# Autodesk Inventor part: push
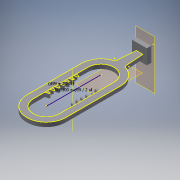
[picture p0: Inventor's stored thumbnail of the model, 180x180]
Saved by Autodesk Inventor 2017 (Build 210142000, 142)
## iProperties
Created: 2017-05
Part Number: push
Material: Generic
Document SubType Name: Modeling
Designer: 1717440
Density: 1 g/cm^3
Appearance: Default
Author: 1717440
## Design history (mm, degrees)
workplane "Work Plane1"
sketch "Sketch1"
  geometry: L1 (0, 3.175)-(17, 3.175) reference; L2 (17, 3.175)-(0, 3.175); L3 (0, 3.175)-(0, 20.175); L4 (0, 20.175)-(17, 20.175); L5 (17, 20.175)-(17, 3.175); 1 further point
  constraints: 8 end point, 2 parallel, 1 horizontal, 1 perpendicular
  dimensions: "d0" = 17 distance of L2.end L3.end
extrude "Extrusion1" new body sketch "Sketch1" distance "d1" = 5; taper "d2" = 0 deg
workplane "Work Plane2"
sketch "Sketch2" dims "d68" = 10, "d80" = 10
  geometry: L1 (-38.705, -3.689)-(1.295, -3.689); L2 (-18.705, -3.689)-(-18.705, 6.001); L3 (-39.255, -7.416)-(-39.255, 0.038); L4 (68.82, -3.689)-(5.82, -3.689); L5 (68.82, 11.311)-(5.82, 11.311); L6 (5.82, -18.689)-(68.82, -18.689); L7 (5.82, 11.311)-(8.32, 6.981); L8 (5.82, 11.311)-(10.82, 11.311); L9 (8.32, 6.981)-(9.82, 6.981); L10 (9.82, 6.981)-(12.32, 11.311); L11 (5.82, 11.311)-(12.32, 11.311); L12 (13.92, 11.311)-(16.42, 6.981); L13 (16.42, 6.981)-(17.92, 6.981); L14 (17.92, 6.981)-(20.42, 11.311); L15 (13.92, 11.311)-(20.42, 11.311); L16 (22.02, 11.311)-(24.52, 6.981); L17 (24.52, 6.981)-(26.02, 6.981); L18 (26.02, 6.981)-(28.52, 11.311); L19 (22.02, 11.311)-(28.52, 11.311); L20 (30.12, 11.311)-(32.62, 6.981); L21 (32.62, 6.981)-(34.12, 6.981); L22 (34.12, 6.981)-(36.62, 11.311); L23 (30.12, 11.311)-(36.62, 11.311); L24 (38.22, 11.311)-(40.72, 6.981); L25 (40.72, 6.981)-(42.22, 6.981); L26 (42.22, 6.981)-(44.72, 11.311); L27 (38.22, 11.311)-(44.72, 11.311); L28 (46.32, 11.311)-(48.82, 6.981); L29 (48.82, 6.981)-(50.32, 6.981); L30 (50.32, 6.981)-(52.82, 11.311); L31 (46.32, 11.311)-(52.82, 11.311); L32 (15.17, 9.146)-(19.17, 9.146); L33 (54.42, 11.311)-(56.92, 6.981); L34 (56.92, 6.981)-(58.42, 6.981); L35 (58.42, 6.981)-(60.92, 11.311); L36 (54.42, 11.311)-(60.92, 11.311); L37 (59.67, 9.146)-(55.67, 9.146); L38 (13.82, -18.689)-(16.32, -14.359); L39 (13.82, -18.689)-(18.82, -18.689); L40 (16.32, -14.359)-(17.82, -14.359); L41 (17.82, -14.359)-(20.32, -18.689); L42 (13.82, -18.689)-(20.32, -18.689); L43 (21.82, -18.689)-(28.32, -18.689); L44 (25.82, -14.359)-(28.32, -18.689); L45 (24.32, -14.359)-(25.82, -14.359); L46 (21.82, -18.689)-(24.32, -14.359); L47 (29.82, -18.689)-(36.32, -18.689); L48 (33.82, -14.359)-(36.32, -18.689); L49 (32.32, -14.359)-(33.82, -14.359); L50 (29.82, -18.689)-(32.32, -14.359); L51 (37.82, -18.689)-(44.32, -18.689); L52 (41.82, -14.359)-(44.32, -18.689); L53 (40.32, -14.359)-(41.82, -14.359); L54 (37.82, -18.689)-(40.32, -14.359); L55 (45.82, -18.689)-(52.32, -18.689); L56 (49.82, -14.359)-(52.32, -18.689); L57 (48.32, -14.359)-(49.82, -14.359); L58 (45.82, -18.689)-(48.32, -14.359); L59 (53.82, -18.689)-(60.32, -18.689); L60 (57.82, -14.359)-(60.32, -18.689); L61 (56.32, -14.359)-(57.82, -14.359); L62 (53.82, -18.689)-(56.32, -14.359); L63 (61.82, -18.689)-(68.32, -18.689); L64 (65.82, -14.359)-(68.32, -18.689)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; A1 r 15 centre (68.82, -3.689) between (68.82, -18.689) and (68.82, 11.311); A2 r 15 centre (5.82, -3.689) between (5.82, 11.311) and (5.82, -18.689); A3 r 22.5 centre (5.82, -3.689) between (-15.485, -10.922) and (5.82, -26.189); A4 r 22.5 centre (68.82, -3.689) between (68.82, -26.189) and (68.82, 18.811); A5 r 3 centre (-18.326, -11.887) between (-15.485, -10.922) and (-18.117, -8.894); A6 r 3 centre (-18.326, 4.509) between (-18.117, 1.516) and (-15.485, 3.545); A7 r 22.5 centre (5.82, -3.689) between (5.82, 18.811) and (-15.485, 3.545); 5 further points
  constraints: 154 end point, 17 point on circle, 10 horizontal, 10 midpoint, 7 centre point, 6 tangent, 5 point on line, 4 symmetric about line, 3 equal length, 2 collinear, 2 parallel, 1 perpendicular, 1 vertical, 101 other
  dimensions: "d45" = 30 diameter of A2; "d46" = 93 distance of point (83.82, -3.689) point (-9.18, -3.689); "d47" = 40 distance of L1.start L1.end; "d54" = 7.45397 distance of L3.start L3.end; "d59" = 5 distance of L5.end L7.end; "d60" = 60 deg angle of L7 L8; "d61" = 1.5 distance of L7.end L9.end; "d62" = 120 deg angle of L10 L9; "d65" = 8.1 distance of L5.end L12.start; "d70" = 5 distance of L38.start L38.end; "d71" = 60 deg angle of L39 L38; "d72" = 8 distance of L6.start L38.start; "d73" = 1.5 distance of L38.end L40.end; "d74" = 120 deg angle of L40 L41; "d77" = 8 distance of L38.start L43.start; "d82" = 7.5 radial gap between concentric circles of A1 A4; "d83" = 28 distance of L3.start L75.end; "d84" = 4 deg angle of L71 L72; "d85" = 28 distance of L3.end L75.start; "d86" = 4 deg angle of L74 L73; "d87" = 3 radius of A5 (derived); "d109" = 45 distance between parallel lines of L70 L69 (derived)
extrude "Extrusion6" join sketch "Sketch2" distance "d88" = 5; taper "d89" = 0 deg
sketch "Sketch3"
  geometry: L1 (-3.689, -68.82)-(-3.689, -5.82); L2 (7.416, -74.703)-(-14.794, -74.703); L3 (-14.794, -74.703)-(-14.794, 0.062); L4 (-14.794, 0.062)-(7.416, 0.062); L5 (7.416, 0.062)-(7.416, -74.703); L6 (7.416, -74.703)-(-14.794, 0.062); L7 (-14.794, -74.703)-(7.416, 0.062); A1 r 15 centre (-3.689, -5.82) between (11.311, -5.82) and (-18.689, -5.82) reference; A2 r 15 centre (-3.689, -68.82) between (-18.689, -68.82) and (11.311, -68.82) reference; 2 further points
  constraints: 14 end point, 3 midpoint, 2 parallel, 1 horizontal, 1 perpendicular, 1 vertical
extrude "Extrusion7" cut sketch "Sketch3" stored distance "d90" = 0; taper "d91" = 0 deg
sketch "Sketch4"
  geometry: L1 (7.416, -48.569)-(7.416, -50.572) reference; L2 (7.416, -50.572)-(11.311, -52.82) reference; L3 (11.311, -52.82)-(11.311, -54.42) reference; L4 (11.311, -54.42)-(9.146, -55.67) reference; L5 (9.146, -55.67)-(9.146, -59.67) reference; L6 (9.146, -59.67)-(11.311, -60.92) reference; L7 (-18.689, -68.32)-(-14.794, -66.072) reference; L8 (-14.794, -66.072)-(-14.794, -64.069) reference; L9 (-14.794, -64.069)-(-18.689, -61.82) reference; L10 (-18.689, -61.82)-(-18.689, -60.32) reference; L11 (-18.689, -60.32)-(-16.524, -59.07) reference; L12 (-16.524, -59.07)-(-16.524, -55.07) reference; L13 (-16.524, -55.07)-(-18.689, -53.82) reference; L14 (-18.689, -53.82)-(-18.689, -52.32) reference; L15 (-18.689, -52.32)-(-14.794, -50.072) reference; L16 (-14.794, -50.072)-(-14.794, -48.069) reference; L17 (-14.794, -48.069)-(-18.689, -45.82) reference; L18 (-18.689, -45.82)-(-18.689, -44.32) reference; L19 (-18.689, -44.32)-(-14.794, -42.072) reference; L20 (-14.794, -42.072)-(-14.794, -40.069) reference; L21 (-14.794, -40.069)-(-18.689, -37.82) reference; L22 (-18.689, -37.82)-(-18.689, -36.32) reference; L23 (-18.689, -36.32)-(-14.794, -34.072) reference; L24 (-14.794, -34.072)-(-14.794, -32.069) reference; L25 (-14.794, -32.069)-(-18.689, -29.82) reference; L26 (-18.689, -29.82)-(-18.689, -28.32) reference; L27 (-18.689, -28.32)-(-14.794, -26.072) reference; L28 (-14.794, -26.072)-(-14.794, -24.069) reference; L29 (-14.794, -24.069)-(-18.689, -21.82) reference; L30 (-18.689, -21.82)-(-18.689, -20.32) reference; L31 (-18.689, -20.32)-(-16.524, -19.07) reference; L32 (-16.524, -19.07)-(-16.524, -15.07) reference; L33 (-16.524, -15.07)-(-18.689, -13.82) reference; L34 (11.311, -5.82)-(7.416, -8.069) reference; L35 (7.416, -8.069)-(7.416, -10.072) reference; L36 (7.416, -10.072)-(11.311, -12.32) reference; L37 (11.311, -12.32)-(11.311, -13.92) reference; L38 (11.311, -13.92)-(9.146, -15.17) reference; L39 (9.146, -15.17)-(9.146, -19.17) reference; L40 (9.146, -19.17)-(11.311, -20.42) reference; L41 (11.311, -20.42)-(11.311, -22.02) reference; L42 (11.311, -22.02)-(7.416, -24.269) reference; L43 (7.416, -24.269)-(7.416, -26.272) reference; L44 (7.416, -26.272)-(11.311, -28.52) reference; L45 (11.311, -28.52)-(11.311, -30.12) reference; L46 (11.311, -30.12)-(7.416, -32.369) reference; L47 (7.416, -32.369)-(7.416, -34.372) reference; L48 (7.416, -34.372)-(11.311, -36.62) reference; L49 (11.311, -36.62)-(11.311, -38.22) reference; L50 (11.311, -38.22)-(7.416, -40.469) reference; L51 (7.416, -40.469)-(7.416, -42.472) reference; L52 (7.416, -42.472)-(11.311, -44.72) reference; L53 (11.311, -44.72)-(11.311, -46.32) reference; L54 (11.311, -46.32)-(7.416, -48.569) reference; L55 (-18.689, -68.32)-(-18.689, -68.82) reference; L56 (-3.689, -68.82)-(-18.689, -68.32); L57 (-18.689, -5.82)-(-18.689, -13.82) reference; L58 (-18.689, -68.32)-(-18.689, -5.82); L59 (-18.689, -5.82)-(11.311, -5.82); L60 (11.311, -68.82)-(11.311, -60.92) reference; L61 (-3.689, -68.82)-(11.311, -68.82); L62 (11.311, -68.82)-(11.311, -5.82); A1 r 22.5 centre (-3.689, -68.82) between (-26.189, -68.82) and (18.811, -68.82) reference; 1 further point
  constraints: 10 end point, 2 perpendicular, 1 collinear, 1 horizontal
extrude "Extrusion8" cut sketch "Sketch4" distance "d92" = 10; taper "d93" = 0 deg
sketch "Sketch5"
  geometry: L1 (-7.454, 38.705)-(0.077, 38.705) reference; L2 (-7.454, 38.705)-(-8.894, 18.117) reference; L3 (-26.189, -5.82)-(-26.189, -68.82) reference; L4 (18.811, -68.82)-(18.811, -5.82) reference; L5 (1.516, 18.117)-(0.077, 38.705) reference; L6 (-18.689, -68.82)-(-18.689, -5.82) reference; L7 (11.311, -5.82)-(11.311, -68.82) reference; A1 r 3 centre (-11.887, 18.326) between (-10.922, 15.485) and (-8.894, 18.117) reference; A2 r 22.5 centre (-3.689, -5.82) between (-10.922, 15.485) and (-26.189, -5.82) reference; A3 r 22.5 centre (-3.689, -68.82) between (-26.189, -68.82) and (18.811, -68.82) reference; A4 r 22.5 centre (-3.689, -5.82) between (18.811, -5.82) and (3.545, 15.485) reference; A5 r 3 centre (4.509, 18.326) between (1.516, 18.117) and (3.545, 15.485) reference; A6 r 15 centre (-3.689, -5.82) between (11.311, -5.82) and (-18.689, -5.82) reference; A7 r 15 centre (-3.689, -68.82) between (-18.689, -68.82) and (11.311, -68.82) reference; 1 further point
sketch "Sketch6"
  geometry: L1 (-18.689, -68.82)-(-18.689, -5.82) reference; L2 (11.311, -5.82)-(11.311, -68.82) reference; L3 (-18.689, -37.32)-(-12.468, -37.32); L4 (-18.689, -37.32)-(-14.613, -37.32); L5 (-14.613, -37.32)-(-14.613, -36.659); L6 (-14.613, -36.659)-(-18.689, -35.676); L7 (-18.689, -5.82)-(-18.689, -68.82) reference; A1 r 15 centre (-3.689, -5.82) between (11.311, -5.82) and (-18.689, -5.82) reference; A2 r 15 centre (-3.689, -68.82) between (-18.689, -68.82) and (11.311, -68.82) reference; 1 further point
  constraints: 8 end point, 2 point on line, 1 horizontal, 1 midpoint, 1 vertical
extrude "Extrusion9" join sketch "Sketch6" stored distance "d94" = 10; taper "d95" = 0 deg
mirror "Mirror1"
pattern_linear "Rectangular Pattern1" dims "d98" = 5.5
sketch "Sketch7"
  geometry: L1 (-7.454, 38.705)-(0.077, 38.705) reference; L2 (-7.454, 38.705)-(-8.894, 18.117) reference; L3 (-26.189, -5.82)-(-26.189, -68.82) reference; L4 (18.811, -68.82)-(18.811, -5.82) reference; L5 (1.516, 18.117)-(0.077, 38.705) reference; L6 (-18.689, -68.82)-(-18.689, -55.464) reference; L7 (-14.613, -54.481)-(-18.689, -55.464) reference; L8 (-14.613, -54.481)-(-14.613, -53.159) reference; L9 (-14.613, -53.159)-(-18.689, -52.176) reference; L10 (-18.689, -52.176)-(-18.689, -49.964) reference; L11 (-14.613, -48.981)-(-18.689, -49.964) reference; L12 (-14.613, -48.981)-(-14.613, -47.659) reference; L13 (-14.613, -47.659)-(-18.689, -46.676) reference; L14 (-18.689, -46.676)-(-18.689, -44.464) reference; L15 (-14.613, -43.481)-(-18.689, -44.464) reference; L16 (-14.613, -43.481)-(-14.613, -42.159) reference; L17 (-14.613, -42.159)-(-18.689, -41.176) reference; L18 (-18.689, -41.176)-(-18.689, -38.964) reference; L19 (-14.613, -37.981)-(-18.689, -38.964) reference; L20 (-14.613, -37.981)-(-14.613, -36.659) reference; L21 (-14.613, -36.659)-(-18.689, -35.676) reference; L22 (-18.689, -35.676)-(-18.689, -33.464) reference; L23 (-14.613, -32.481)-(-18.689, -33.464) reference; L24 (-14.613, -32.481)-(-14.613, -31.159) reference; L25 (-14.613, -31.159)-(-18.689, -30.176) reference; L26 (-18.689, -30.176)-(-18.689, -27.964) reference; L27 (-14.613, -26.981)-(-18.689, -27.964) reference; L28 (-14.613, -26.981)-(-14.613, -25.659) reference; L29 (-14.613, -25.659)-(-18.689, -24.676) reference; L30 (-18.689, -24.676)-(-18.689, -22.464) reference; L31 (-14.613, -21.481)-(-18.689, -22.464) reference; L32 (-14.613, -21.481)-(-14.613, -20.159) reference; L33 (-14.613, -20.159)-(-18.689, -19.176) reference; L34 (-18.689, -19.176)-(-18.689, -5.82) reference; L35 (11.311, -5.82)-(11.311, -68.82) reference; L36 (-3.689, -68.82)-(-3.689, -5.82); A1 r 3 centre (-11.887, 18.326) between (-10.922, 15.485) and (-8.894, 18.117) reference; A2 r 22.5 centre (-3.689, -5.82) between (-10.922, 15.485) and (-26.189, -5.82) reference; A3 r 22.5 centre (-3.689, -68.82) between (-26.189, -68.82) and (18.811, -68.82) reference; A4 r 22.5 centre (-3.689, -5.82) between (18.811, -5.82) and (3.545, 15.485) reference; A5 r 3 centre (4.509, 18.326) between (1.516, 18.117) and (3.545, 15.485) reference; A6 r 15 centre (-3.689, -5.82) between (11.311, -5.82) and (-18.689, -5.82) reference; A7 r 15 centre (-3.689, -68.82) between (-18.689, -68.82) and (11.311, -68.82) reference; 4 further points
  constraints: 2 end point, 1 coincident, 1 midpoint, 1 vertical
  dimensions: "d99" = 2.212 distance of L18.end L17.end (derived); "d100" = 1.106 vertical distance of point (-3.689, -37.32) point (-3.727, -38.426) (= 0.5 x d99)
workaxis "Work Axis1"
pattern_circular "Circular Pattern1" dims angle "d102" = 360 deg
sketch "Sketch8"
  geometry: L1 (-14.613, -48.981)-(-18.689, -49.964) reference; L2 (-14.613, -48.981)-(-14.613, -47.659) reference; L3 (-14.613, -47.659)-(-18.689, -46.676) reference; L4 (-14.613, -21.481)-(-14.613, -20.159) reference; L5 (-14.613, -20.159)-(-18.689, -19.176) reference; L6 (-17.241, -49.615)-(-16.651, -47.168); L7 (-18.689, -22.464)-(-14.613, -21.481) reference; L8 (-17.241, -22.115)-(-17.241, -19.526); 1 further point
  constraints: 4 end point, 3 point on line, 1 midpoint, 1 vertical
extrude "Extrusion10" cut sketch "Sketch8" distance "d104" = 10; taper "d105" = 0 deg
pattern_circular "Circular Pattern2" dims angle "d107" = 360 deg
body "Solid1"
node "Reference1"
